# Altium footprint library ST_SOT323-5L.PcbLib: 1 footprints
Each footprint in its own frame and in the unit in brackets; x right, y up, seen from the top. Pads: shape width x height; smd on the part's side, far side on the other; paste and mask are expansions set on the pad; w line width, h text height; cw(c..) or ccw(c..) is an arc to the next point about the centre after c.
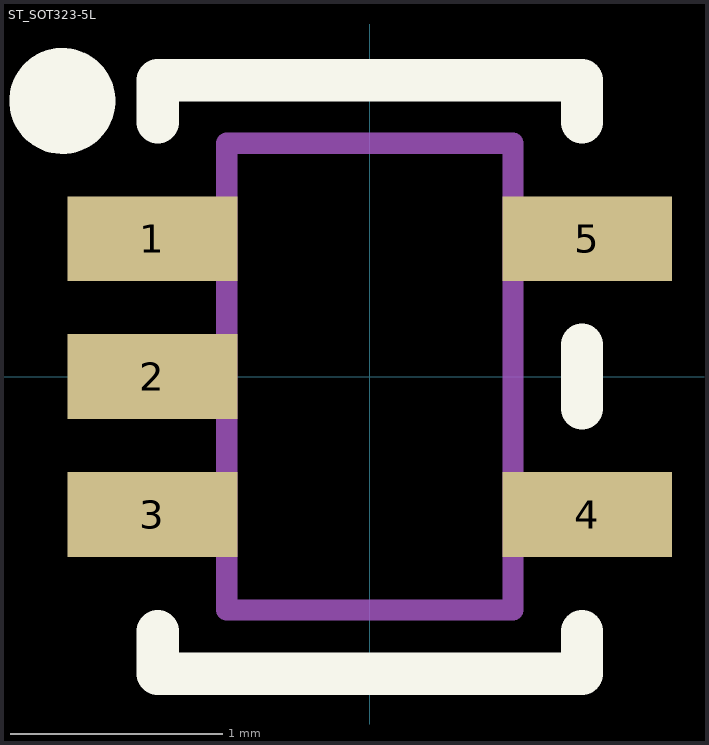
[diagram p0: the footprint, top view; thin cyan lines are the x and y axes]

## ST_SOT323-5L [mm]
height 1.1
pads (5):
  rect 0.8x0.4 smd: 1(-1.025,0.65) 2(-1.025,0) 3(-1.025,-0.65) 4(1.025,-0.65) 5(1.025,0.65)
Top Overlay:
  circle w0.25: c-1.45,1.3 r0.125
  lines w0.2: -1,-1.2 -1,-1.4 -0.437,-1.4 0.437,-1.4 1,-1.4 1,-1.2 ; -1,1.2 -1,1.397 1,1.397 1,1.2 ; 1,-0.15 1,0.15
Mechanical 13:
  lines w0.1: -0.675,-1.1 -0.675,1.1 0.675,1.1 0.675,-1.1 -0.675,-1.1
3D body "ST_SOT323-5L.step": height 1.1, standoff 0, extent -1.2,-1.1 1.2,1.1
